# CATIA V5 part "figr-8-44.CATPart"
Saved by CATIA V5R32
Part number: Part1
Bounding box of the stored display mesh (mm): x -50 to 50, y -50 to 50, z 0 to 25
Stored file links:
  D:\PROJECTS\Project 2022\CATIA V5 6R 2022\Resources\Part Files\c08_catia_v5_6r2022_prt\figr-8-44.CATPart
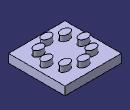
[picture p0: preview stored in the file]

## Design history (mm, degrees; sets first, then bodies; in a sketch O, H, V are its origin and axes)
Body1 (main body)
  Sketch1 on xy-plane, origin (0, 0, 0), H (1, 0, 0), V (0, 1, 0)
    line L1 (-50, 50) -> (50, 50)
    line L2 (50, 50) -> (50, -50)
    line L3 (50, -50) -> (-50, -50)
    line L4 (-50, -50) -> (-50, 50)
    axis line L5 (50, -50) -> (-50, 50)
    length L2 = 100
    length L3 = 100
    horizontal: L1 H, L3 H
    vertical: L2 V, L4 V
    midpoint: L5 O
  Pad1: profile Sketch1, direction (0, 0, 1), length 15
  Sketch2 on face of Pad1, origin (0, 0, 15), H (1, 0, 0), V (0, 1, 0)
    point P1 (0, -32.9864)
    ellipse A1 centre (0, -32.9864) semi-axes 9.9006, 6.5465 rotation 0
    point P2 (0, -26.4399)
    coincidence: P1 V, P2 V, A1 P2
  Pad2: profile Sketch2, direction (0, 0, 1), length 10
  CircPattern1: of Pad2, instances 8, angular step 45 {= 360.0*1 deg/CircPattern1.AngularNumber}, axis from edge of Sketch3
  Sketch3 on yz-plane, origin (0, 0, 0), H (0, 1, 0), V (0, 0, 1)
    line L1 (0, 0) -> (0, 18.4864)
    vertical: L1 V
